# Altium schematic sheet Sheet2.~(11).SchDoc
size A
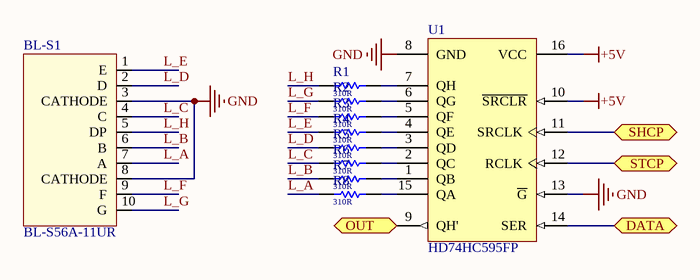
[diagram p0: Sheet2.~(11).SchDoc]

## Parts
BL-S1  BL-S56A-11UR  [BL-S56A-11UR]
R1  310R  [Res0805]
R2  310R  [Res0805]
R3  310R  [Res0805]
R4  310R  [Res0805]
R5  310R  [Res0805]
R6  310R  [Res0805]
R7  310R  [Res0805]
R8  310R  [Res0805]
U1  HD74HC595FP  [PRSP0016DH-B_N]

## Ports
DATA, OUT (out), SHCP, STCP

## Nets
+5V: U1.10(~{SRCLR}) U1.16(VCC)
GND: BL-S1.3(CATHODE) BL-S1.8(CATHODE) U1.8(GND) U1.13(~{G})
DATA: U1.14(SER) ; port DATA
L_A: BL-S1.7(A) R8.1
L_B: BL-S1.6(B) R7.1
L_C: BL-S1.4(C) R6.1
L_D: BL-S1.2(D) R5.1
L_E: BL-S1.1(E) R4.1
L_F: BL-S1.9(F) R3.1
L_G: BL-S1.10(G) R2.1
L_H: BL-S1.5(DP) R1.1
OUT: U1.9(QH') ; port OUT
SHCP: U1.11(SRCLK) ; port SHCP
STCP: U1.12(RCLK) ; port STCP
NetR1_2: R1.2 U1.7(QH)
NetR2_2: R2.2 U1.6(QG)
NetR3_2: R3.2 U1.5(QF)
NetR4_2: R4.2 U1.4(QE)
NetR5_2: R5.2 U1.3(QD)
NetR6_2: R6.2 U1.2(QC)
NetR7_2: R7.2 U1.1(QB)
NetR8_2: R8.2 U1.15(QA)

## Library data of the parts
BL-S1 = Component_1
R1-R8 = Res1: Resistor
U1 = HD74HC595FP: 8-bit Shift Register / Latch with 3-State Outputs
